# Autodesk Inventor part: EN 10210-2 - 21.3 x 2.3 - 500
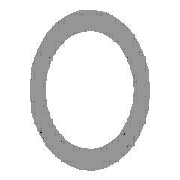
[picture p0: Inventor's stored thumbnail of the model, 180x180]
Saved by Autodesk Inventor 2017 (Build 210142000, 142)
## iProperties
Created: 2017-11
Part Number: EN 10210-2 - 21.3 x 2.3 - 500
Material: Steel, Mild
Description: Pipe
Document SubType Name: Modeling
Standard: DIN
Designer: iusti
Standard Revision: 2006-07
Standards Organization: DIN
Language: en-US
Size Designation: 21.3 x 2.3
Categories: <MemberInstance><Categories><Category DisplayName="Structural Shapes" InternalName="089c4875-fa83-4c05-b084-43b9cc11f5ed" Mnemonic="GRDR"><CategoryParameter Dis
Stock Number: 21.3 x 2.3
Density: 7.85 g/cm^3
Appearance: Semi-Polished
_CCFamilyMember: 1
_CCFamilyDisplayName: DIN EN 10210-2 - Pipe
_FrameMemberDoc: Frame Member File
_Version: 15.0.0
_GetPNFromCC: 1
G_L: 500.000 mm
G_W: 21.300 mm
G_H: 21.300 mm
IsCustomPart: 1
Author: iusti
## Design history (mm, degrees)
node "Start plane"
node "End plane"
sketch "Sketch"
  geometry: C1 r 8.35 at (0, 0); C2 r 10.65 at (0, 0); 2 further points
  constraints: 3 coincident, 2 centre point
  dimensions: "d0" = 21.3 diameter of C2 (= G_H); "d1" = 2.3 radial gap between concentric circles of C2 C1 (= G_T)
extrude "Body" new body sketch "Sketch" stored distance "d2" = 500 (= G_L); taper "d3" = 0 deg
node "Driven Length"
  sketch "Sketch3"
    geometry: L1 (0, 0)-(10, 0) reference
    constraints: 2 end point, 1 horizontal
  workplane "Work Plane3"
  sketch "Sketch4"
    geometry: L1 (-2, 0)-(12, 0) reference; L2 (-2, 500)-(12, 500) reference
    dimensions: "d7" = 500 distance between parallel lines of L1 L2 (derived)
body "Solid1"
other parameters: "G_H" = 21.3 [user parameter; used in 1 equation term], "G_T" = 2.3 [user parameter; used in 1 equation term], "G_L" = 500 (= d7) [user parameter; used in 1 equation term], "G_OFFSET_START" = 0 [user parameter; used in 1 equation term], "G_OFFSET_END" = 0 [user parameter; used in 1 equation term], "d4" = 0 (computed from G_OFFSET_START), "d6" = 90 deg
